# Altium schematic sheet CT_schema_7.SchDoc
size 257 x 245 mm
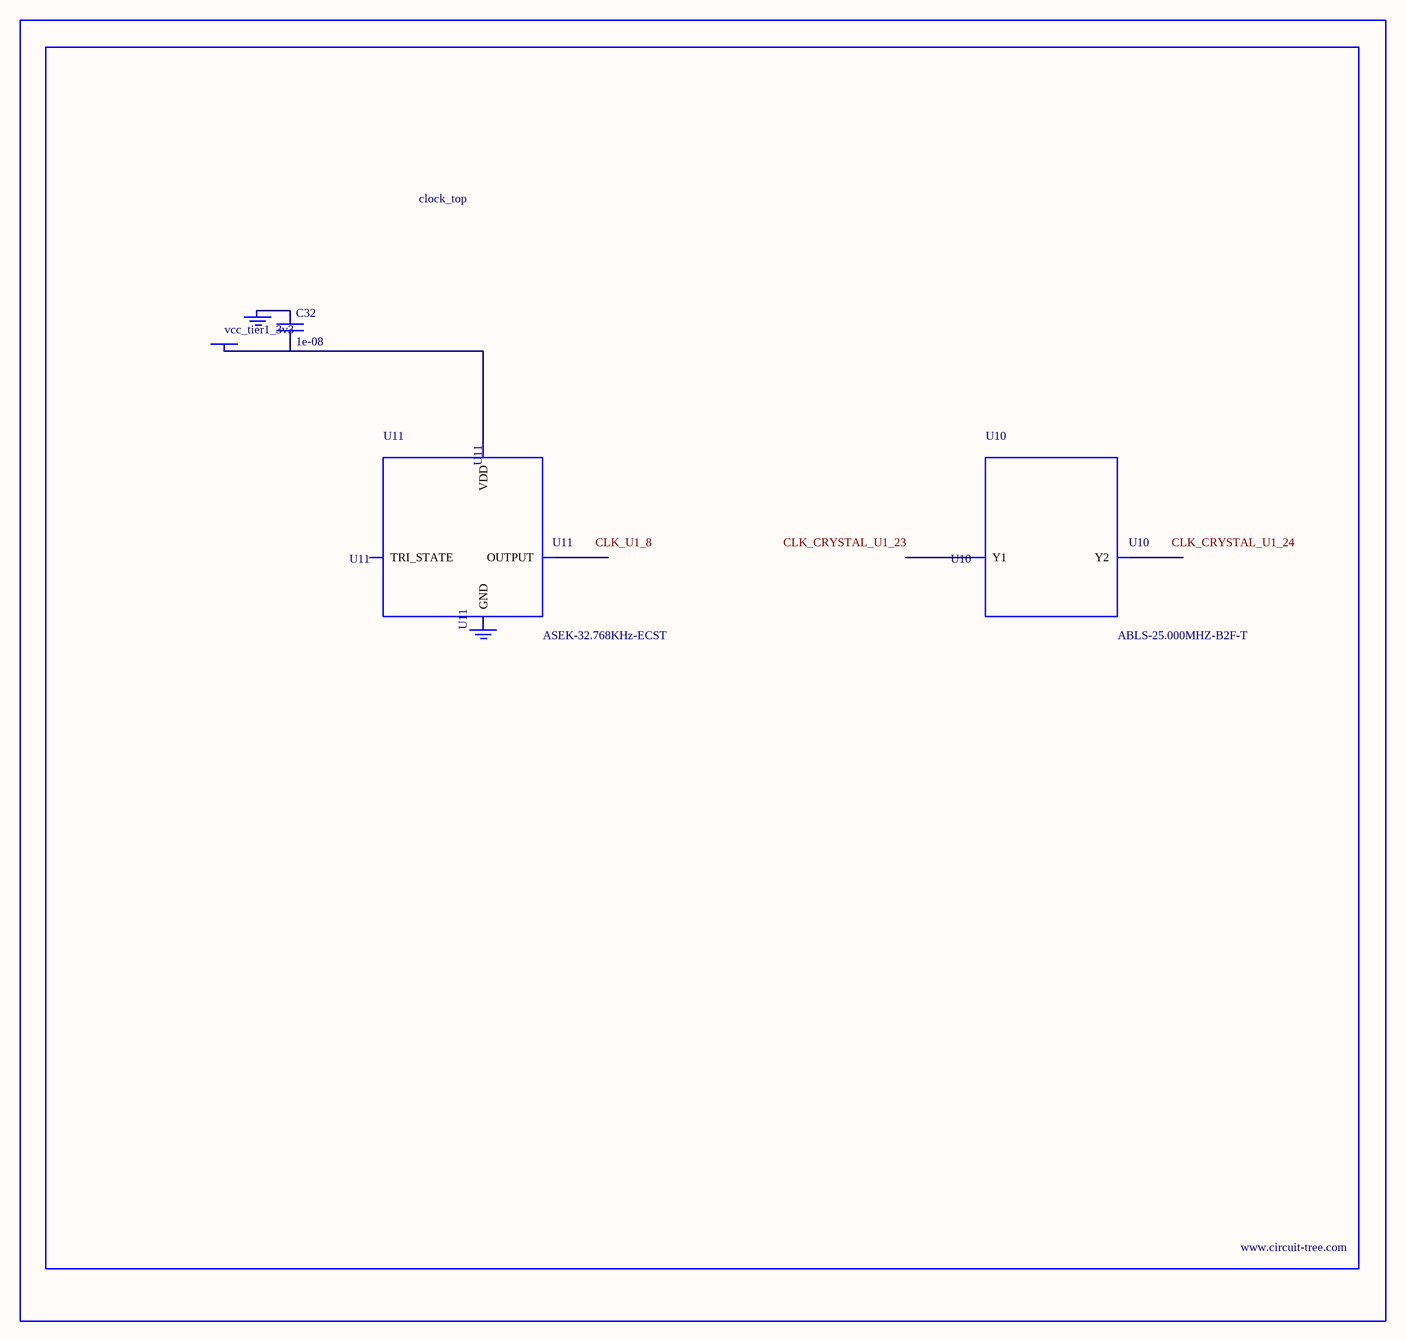
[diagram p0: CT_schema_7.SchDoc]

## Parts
BORDER6  (no value)
C32  1e-08  [C0402]
GND_INSTANCE_6_0  (no value)
GND_INSTANCE_6_1  (no value)
POWER_INSTANCE_6_0  vcc_tier1_3v3
U10  ABLS-25.000MHZ-B2F-T  [ABLS-25.000MHZ-B2F-T]
U11  ASEK-32.768KHz-ECST  [ASEK]

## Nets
NetC32_1: C32.1 GND_INSTANCE_6_0.0(GND)
NetC32_2: C32.2 POWER_INSTANCE_6_0.0(PWR) U11.4(VDD)

Not connected (* = marked no-connect by the designer): GND_INSTANCE_6_1 0(GND); U10 1(Y1) 2(Y2); U11 1(TRI_STATE) 2(GND) 3(OUTPUT)

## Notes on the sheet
- Labels drawn without touching a wire or pin: CLK_CRYSTAL_U1_23, CLK_CRYSTAL_U1_24, CLK_U1_8

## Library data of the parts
BORDER6 = BORDER_PAGE6
C32 = C0402C103K3RAC
GND_INSTANCE_6_0 GND_INSTANCE_6_1 = GND
POWER_INSTANCE_6_0 = PWR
